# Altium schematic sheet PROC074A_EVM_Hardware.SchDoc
size 431 x 279 mm; Date: Not shown in title block; ApprovedBy: Not shown in title block; CheckedBy: Not shown in title block; Author: Not shown in title block; CompanyName: Not shown in title block; Engineer: Not shown in title block; Organization: Not shown in title block; Address1: Not shown in title block; Address2: Not shown in title block; Address3: Not shown in title block; Address4: Not shown in title block; DocumentNumber: 1; Revision: Use project parameter SCH_Rev; SheetNumber: 22; SheetTotal: 22; PageSetup: Record=PageOptions¦CenterHorizontal=True¦CenterVertical=True¦PrintScale=1.00¦XCorrection=1.00¦YCorrection=1.00¦PrintKind=0¦BorderSize=5000000¦LeftOffset=0¦BottomOffset=0¦Orientation=2¦PaperLength=1000¦PaperWidth=1000¦Scale=100¦PaperSource=15¦PrintQuality=600¦MediaType=1¦DitherType=10¦PaperKind=Letter¦PrintScaleMode=1
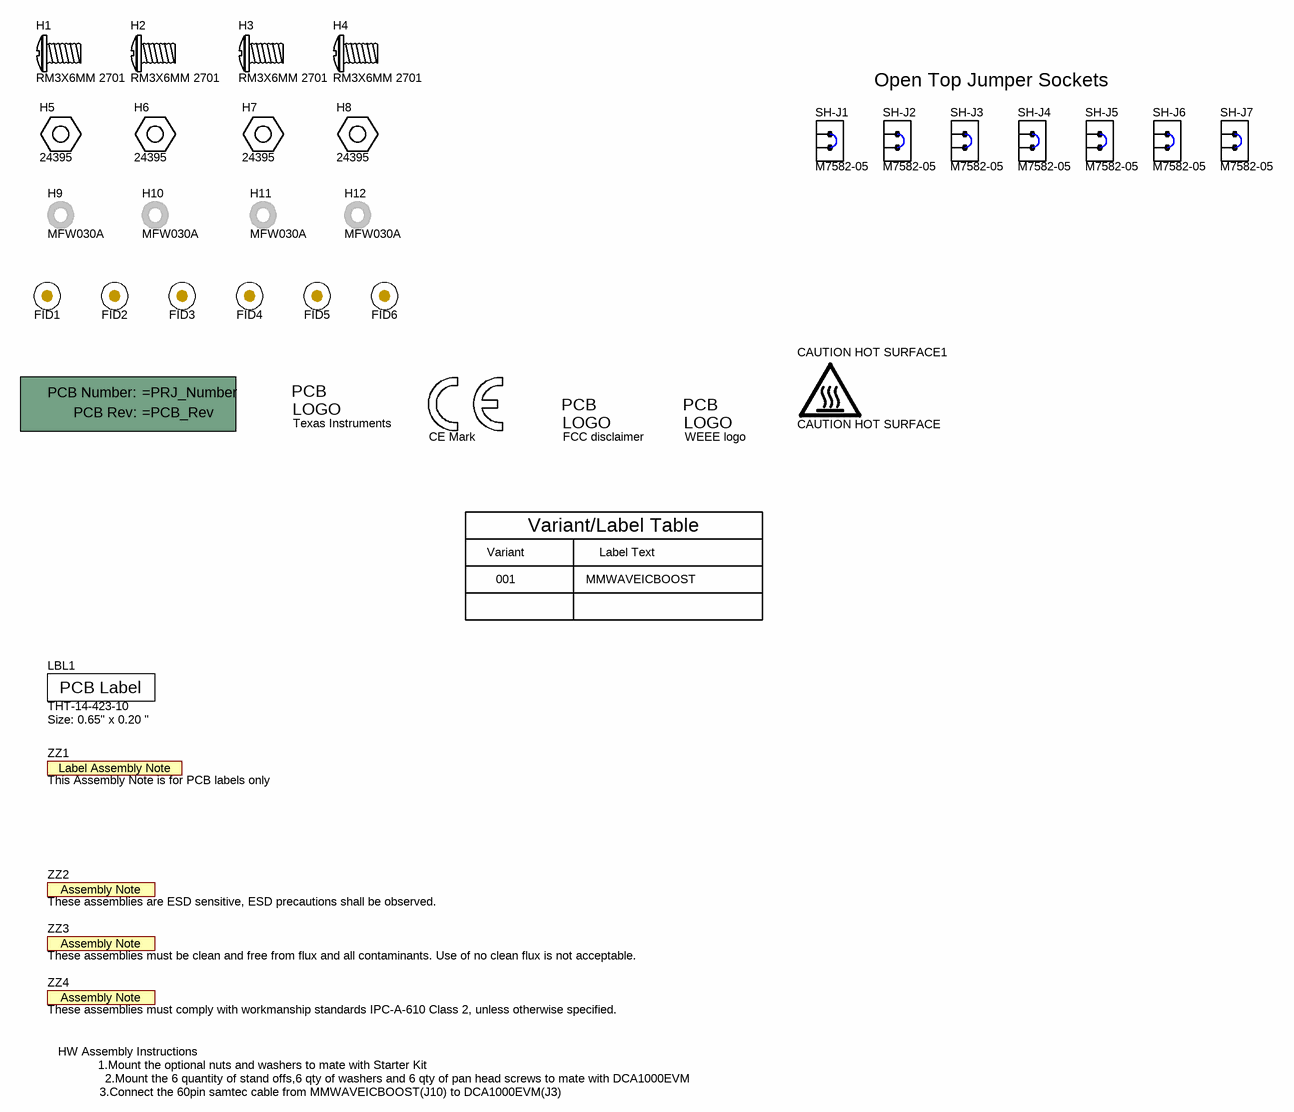
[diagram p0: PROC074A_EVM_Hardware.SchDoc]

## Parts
!PCB  Printed Circuit Board  (value not drawn)  (mechanical)
CAUTION_HOT_SURFACE1  CAUTION HOT SURFACE  [IEC_HotSurface_Small]  (no BOM)
FID1  Fiducial  [Fiducial10-20]  (value not drawn)
FID2  Fiducial  [Fiducial10-20]  (value not drawn)
FID3  Fiducial  [Fiducial10-20]  (value not drawn)
FID4  Fiducial  [Fiducial10-20]  (value not drawn)
FID5  Fiducial  [Fiducial10-20]  (value not drawn)
FID6  Fiducial  [Fiducial10-20]  (value not drawn)
H1  RM3X6MM 2701  (mechanical)
H2  RM3X6MM 2701  (mechanical)
H3  RM3X6MM 2701  (mechanical)
H4  RM3X6MM 2701  (mechanical)
H5  24395  (mechanical)
H6  24395  (mechanical)
H7  24395  (mechanical)
H8  24395  (mechanical)
H9  MFW030A  (mechanical)
H10  MFW030A  (mechanical)
H11  MFW030A  (mechanical)
H12  MFW030A  (mechanical)
LBL1  THT-14-423-10  Note: Size: 0.65" x 0.20 "  [Label_650x200]
Logo1  Texas Instruments  [TI_Stacked_Overlay_Small]  (no BOM)
Logo2  CE Mark  [CE_Mark_5mm]  (no BOM)
Logo3  FCC disclaimer  [FCC_disclaimer]  (no BOM)
Logo4  WEEE logo  [WEEE_Minimum]  (no BOM)
SH-J1  M7582-05  [Harwin_M7582-05]  (mechanical)
SH-J2  M7582-05  [Harwin_M7582-05]  (mechanical)
SH-J3  M7582-05  [Harwin_M7582-05]  (mechanical)
SH-J4  M7582-05  [Harwin_M7582-05]  (mechanical)
SH-J5  M7582-05  [Harwin_M7582-05]  (mechanical)
SH-J6  M7582-05  [Harwin_M7582-05]  (mechanical)
SH-J7  M7582-05  [Harwin_M7582-05]  (mechanical)
ZZ1  This Assembly Note is for PCB labels only  [AssemblyNoteLabel]  (no BOM)
ZZ2  These assemblies are ESD sensitive, ESD precautions shall be observed.  [AssemblyNote]  (no BOM)
ZZ3  These assemblies must be clean and free from flux and all contaminants. Use of no clean flux is not acceptable.  [AssemblyNote]  (no BOM)
ZZ4  These assemblies must comply with workmanship standards IPC-A-610 Class 2, unless otherwise specified.  [AssemblyNote]  (no BOM)

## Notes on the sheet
- Open Top Jumper Sockets
- Variant
- 001
- Variant/Label Table
- Label Text
- MMWAVEICBOOST
- (near ZZ4) HW Assembly Instructions
- 1.Mount the optional nuts and washers to mate with Starter Kit
- 3.Connect the 60pin samtec cable from MMWAVEICBOOST(J10) to DCA1000EVM(J3)
- 2.Mount the 6 quantity of stand offs,6 qty of washers and 6 qty of pan head screws to mate with DCA1000EVM

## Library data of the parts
!PCB = CMP-0003618-2: Manufacturer: Any
CAUTION_HOT_SURFACE1 = CMP-0074837-1: IEC 61010-1 Hot Surface Warning; Library Reference: IEC_HotSurface; SymbolCreator: a0412235
FID1-FID6 = CMP-0077181-1: Fiducial mark.  There is nothing to buy or mount.
H1-H4 = CMP-0077936-1: MACHINE SCREW PAN PHILLIPS M3; Manufacturer: APM HEXSEAL; CompType: Standoff
H5-H8 = CMP-0084033-1: HEX STANDOFF M3 BRASS 15MM; Manufacturer: Keystone; CompType: Hardware
H9-H12 = CMP-0003900-1: WASHER FLAT M3 NYLON; Manufacturer: Essentra Components
LBL1 = CMP-0003625-1: Thermal Transfer Printable Labels, 0.650" W x 0.200" H - 10,000 per roll; Manufacturer: Brady; CompType: Label
Logo1 = CMP-0074838-1: Texas Instrument Corporate Signature; SymbolCreator: a0412235; Lib Reference: TI_Logo; Library Reference: Logo
Logo2 = CMP-0074844-1: SymbolCreator: a0412235
Logo3 = CMP-0074847-1: FCC_disclaimer; Library Reference: Logo
Logo4 = CMP-0074769-1
SH-J1-SH-J7 = CMP-0078738-1: Single Operation 2.54mm Pitch Open Top Jumper Socket; Manufacturer: Harwin; CompType: Shunt
ZZ1 = CMP-0003616-3
ZZ2 = CMP-0077236-1
ZZ3 = CMP-0077237-1
ZZ4 = CMP-0077238-1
